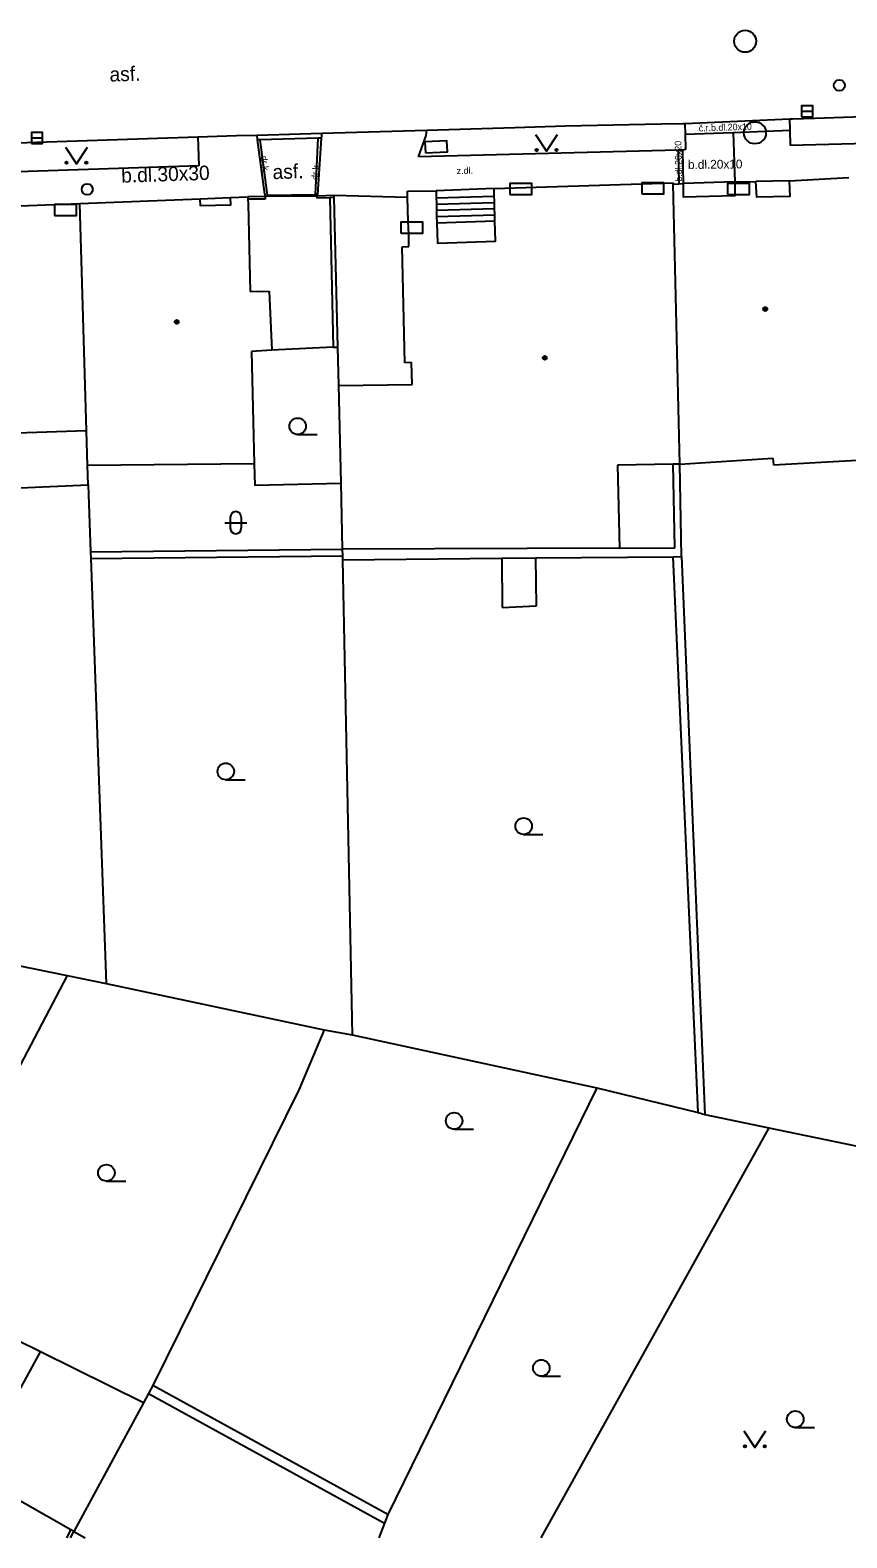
# Model space of a CAD drawing. Extents: x -595546 to -593986, y -1160845 to -1159202.
# Drawn here: x -594974.1 to -594937.1, y -1160843.2 to -1160775 of the extents above; entities that cross this region are included whole.
import ezdxf

# ---------------------------------------------------------------- set-up
doc = ezdxf.new("R2010")
doc.units = 0
for name, color, linetype in [('DOP - kresba z DSPS bez souradnic', 7, 'Continuous'), ('DOP - rozhrani ploch obecne', 7, 'Continuous'), ('Level 24', 7, 'Continuous'), ('Level 27', 7, 'Continuous'), ('Level 28', 7, 'Continuous'), ('Level 36', 7, 'Continuous'), ('Level 39', 7, 'Continuous'), ('TM - budovy zdene_ betonove - NP', 7, 'Continuous'), ('TM - budovy zdene_ betonove - VP', 7, 'Continuous'), ('TM - chodniky - VP', 7, 'Continuous'), ('TM - komunikace - VP', 7, 'Continuous'), ('TM - plot drateny_ kovovy - VP', 7, 'Continuous'), ('TM - podezdivka plotu - VP', 7, 'Continuous'), ('TM - popis povrchu', 7, 'Continuous'), ('TM - rozhrani mezi zpev. plochami mezi sebou - VP', 7, 'Continuous'), ('TM - rozhrani ploch obecne - VP', 7, 'Continuous'), ('TM - schody - VP', 7, 'Continuous'), ('TM - vjezd na pozemek', 7, 'Continuous'), ('TM - vstup do budovy - zdene_ betonove', 7, 'Continuous')]:
    doc.layers.add(name, color=color, linetype=linetype)

msp = doc.modelspace()

# ---------------------------------------------------------------- linework, layer by layer
at = {"layer": 'DOP - kresba z DSPS bez souradnic'}
for points in [[(-594944.87, -1160798.41), (-594944.94, -1160794.62)], [(-594971.35, -1160798.59), (-594959.95, -1160798.46)], [(-594947.38, -1160798.42), (-594944.87, -1160798.41)], [(-594943.81, -1160823.98), (-594944.95, -1160798.81)], [(-594952.71, -1160798.88), (-594951.16, -1160798.86)], [(-594975.24, -1160837.78), (-594973.62, -1160834.82)], [(-594968.73, -1160836.71), (-594958.03, -1160842.58)], [(-594975.4, -1160841.06), (-594972.24, -1160842.87)], [(-594972.24, -1160842.87), (-594972.1, -1160842.95)], [(-594972.1, -1160842.95), (-594971.596, -1160843.241)]]:
    msp.add_lwpolyline(points, dxfattribs=at)
at = {"layer": 'DOP - rozhrani ploch obecne'}
for points in [[(-594971.46, -1160795.55), (-594971.48, -1160794.68)], [(-594944.56, -1160798.8), (-594944.64, -1160794.61)], [(-594979.39, -1160795.9), (-594971.46, -1160795.55)], [(-594971.46, -1160795.55), (-594971.35, -1160798.59)], [(-594971.35, -1160798.59), (-594971.34, -1160798.89)], [(-594971.34, -1160798.89), (-594959.93, -1160798.76)], [(-594959.95, -1160798.46), (-594959.93, -1160798.76)], [(-594959.93, -1160798.76), (-594959.93, -1160798.95)], [(-594951.16, -1160798.86), (-594944.95, -1160798.81)], [(-594944.95, -1160798.81), (-594944.56, -1160798.8)], [(-594944.56, -1160798.8), (-594943.51, -1160824.07)], [(-594971.34, -1160798.89), (-594970.64, -1160818.13)], [(-594959.93, -1160798.95), (-594952.71, -1160798.88)], [(-594959.93, -1160798.95), (-594959.49, -1160820.46)], [(-594952.71, -1160798.88), (-594952.69, -1160801.11)], [(-594951.14, -1160801.03), (-594951.16, -1160798.86)], [(-594952.69, -1160801.11), (-594951.14, -1160801.03)], [(-594978.49, -1160816.54), (-594972.41, -1160817.77)], [(-594972.41, -1160817.77), (-594979.48, -1160831.23)], [(-594972.41, -1160817.77), (-594970.64, -1160818.13)], [(-594970.64, -1160818.13), (-594960.76, -1160820.23)], [(-594960.76, -1160820.23), (-594961.89, -1160822.92), (-594968.53, -1160836.34)], [(-594960.76, -1160820.23), (-594959.49, -1160820.46)], [(-594959.49, -1160820.46), (-594948.41, -1160822.86)], [(-594948.41, -1160822.86), (-594957.88, -1160842.18)], [(-594948.41, -1160822.86), (-594943.81, -1160823.98)], [(-594943.81, -1160823.98), (-594943.51, -1160824.07)], [(-594943.51, -1160824.07), (-594940.6, -1160824.67)], [(-594940.6, -1160824.67), (-594950.935, -1160843.241)], [(-594940.6, -1160824.67), (-594935.43, -1160825.75)], [(-594973.62, -1160834.82), (-594974.72, -1160834.27)], [(-594968.95, -1160837.12), (-594973.62, -1160834.82)], [(-594968.53, -1160836.34), (-594968.73, -1160836.71)], [(-594957.88, -1160842.18), (-594968.53, -1160836.34)], [(-594968.73, -1160836.71), (-594968.95, -1160837.12)], [(-594968.95, -1160837.12), (-594972.1, -1160842.95)], [(-594957.88, -1160842.18), (-594958.03, -1160842.58)], [(-594958.03, -1160842.58), (-594958.284, -1160843.241)]]:
    msp.add_lwpolyline(points, dxfattribs=at)
at = {"layer": 'Level 24'}
for points in [[(-594956.174, -1160780.523), (-594955.175, -1160780.471), (-594955.201, -1160779.972), (-594956.199, -1160780.024)], [(-594952.348, -1160782.399), (-594951.348, -1160782.399), (-594951.348, -1160781.899), (-594952.348, -1160781.899)], [(-594946.367, -1160782.378), (-594945.367, -1160782.378), (-594945.367, -1160781.878), (-594946.367, -1160781.878)], [(-594942.487, -1160782.408), (-594941.487, -1160782.408), (-594941.487, -1160781.908), (-594942.487, -1160781.908)], [(-594972.987, -1160783.358), (-594971.987, -1160783.358), (-594971.987, -1160782.858), (-594972.987, -1160782.858)], [(-594957.288, -1160784.159), (-594956.288, -1160784.159), (-594956.288, -1160783.659), (-594957.288, -1160783.659)]]:
    msp.add_lwpolyline(points, close=True, dxfattribs=at)
at = {"layer": 'Level 27'}
for p, q in [((-594939.12, -1160778.63), (-594938.62, -1160778.63)), ((-594974.03, -1160779.84), (-594973.53, -1160779.84))]:
    msp.add_line(p, q, dxfattribs=at)
for points in [[(-594939.12, -1160778.88), (-594938.62, -1160778.88), (-594938.62, -1160778.38), (-594939.12, -1160778.38)], [(-594974.03, -1160780.09), (-594973.53, -1160780.09), (-594973.53, -1160779.59), (-594974.03, -1160779.59)]]:
    msp.add_lwpolyline(points, close=True, dxfattribs=at)
for centre in [(-594941.68, -1160775.46), (-594941.24, -1160779.61)]:
    msp.add_circle(centre, 0.5, dxfattribs=at)
at = {"layer": 'Level 28'}
for centre in [(-594937.41, -1160777.46), (-594971.5, -1160782.17)]:
    msp.add_circle(centre, 0.25, dxfattribs=at)
at = {"layer": 'Level 36'}
for p, q in [((-594961.96, -1160793.275), (-594961.085, -1160793.275)), ((-594965.266, -1160797.266), (-594964.266, -1160797.266)), ((-594965.016, -1160797.016), (-594965.016, -1160797.516)), ((-594964.516, -1160797.016), (-594964.516, -1160797.516)), ((-594965.22, -1160808.905), (-594964.345, -1160808.905)), ((-594951.72, -1160811.385), (-594950.845, -1160811.385)), ((-594954.87, -1160824.735), (-594953.995, -1160824.735)), ((-594970.63, -1160827.085), (-594969.755, -1160827.085)), ((-594950.92, -1160835.925), (-594950.045, -1160835.925)), ((-594939.41, -1160838.245), (-594938.535, -1160838.245))]:
    msp.add_line(p, q, dxfattribs=at)
for points in [[(-594951.18, -1160779.69), (-594950.68, -1160780.44), (-594950.18, -1160779.69)], [(-594972.49, -1160780.26), (-594971.99, -1160781.01), (-594971.49, -1160780.26)], [(-594941.74, -1160838.4), (-594941.24, -1160839.15), (-594940.74, -1160838.4)]]:
    msp.add_lwpolyline(points, dxfattribs=at)
for centre, radius in [((-594951.13, -1160780.39), 0.05), ((-594950.231, -1160780.39), 0.05), ((-594972.44, -1160780.96), 0.05), ((-594971.541, -1160780.96), 0.05), ((-594961.96, -1160792.9), 0.375), ((-594965.22, -1160808.53), 0.375), ((-594951.72, -1160811.01), 0.375), ((-594954.87, -1160824.36), 0.375), ((-594970.63, -1160826.71), 0.375), ((-594950.92, -1160835.55), 0.375), ((-594939.41, -1160837.87), 0.375), ((-594941.69, -1160839.1), 0.05), ((-594940.791, -1160839.1), 0.05)]:
    msp.add_circle(centre, radius, dxfattribs=at)
for centre, start, end in [((-594964.766, -1160797.016), 0, 180), ((-594964.766, -1160797.516), 180, 0)]:
    msp.add_arc(centre, 0.25, start, end, dxfattribs=at)
at = {"layer": 'Level 39'}
for centre, radius in [((-594940.77, -1160787.59), 0.09), ((-594940.77, -1160787.59), 0.0398), ((-594967.44, -1160788.17), 0.09), ((-594967.44, -1160788.17), 0.0398), ((-594950.76, -1160789.8), 0.09), ((-594950.76, -1160789.8), 0.0398)]:
    msp.add_circle(centre, radius, dxfattribs=at)
at = {"layer": 'TM - budovy zdene_ betonove - NP'}
for points in [[(-594955.69, -1160782.24), (-594955.67, -1160783.12), (-594955.67, -1160783.4), (-594955.66, -1160783.68), (-594955.63, -1160784.6), (-594953, -1160784.52), (-594953.03, -1160783.6), (-594953.03, -1160783.32), (-594953.04, -1160783.03), (-594953.06, -1160782.13)], [(-594942.15, -1160781.83), (-594942.15, -1160782.46), (-594944.47, -1160782.52), (-594944.48, -1160781.91)], [(-594939.69, -1160781.78), (-594939.66, -1160782.5), (-594941.15, -1160782.53), (-594941.19, -1160781.82)], [(-594965.02, -1160782.54), (-594965.01, -1160782.88), (-594966.37, -1160782.92), (-594966.38, -1160782.6)]]:
    msp.add_lwpolyline(points, dxfattribs=at)
at = {"layer": 'TM - budovy zdene_ betonove - VP'}
for points in [[(-594939.69, -1160781.78), (-594936.98, -1160781.63)], [(-594956.99, -1160782.25), (-594955.69, -1160782.24)], [(-594956.98, -1160782.54), (-594956.99, -1160782.25)], [(-594953.06, -1160782.13), (-594944.94, -1160781.88)], [(-594944.94, -1160781.88), (-594944.94, -1160781.93)], [(-594944.94, -1160781.93), (-594944.68, -1160781.92)], [(-594944.64, -1160794.61), (-594944.94, -1160781.93)], [(-594944.68, -1160781.92), (-594944.48, -1160781.91)], [(-594942.15, -1160781.83), (-594941.19, -1160781.82)], [(-594979.78, -1160783.11), (-594977.28, -1160783.021), (-594971.84, -1160782.81)], [(-594971.84, -1160782.81), (-594966.38, -1160782.6)], [(-594971.54, -1160793.11), (-594971.84, -1160782.81)], [(-594966.38, -1160782.6), (-594965.02, -1160782.54)], [(-594965.02, -1160782.54), (-594964.22, -1160782.51)], [(-594964.22, -1160782.51), (-594964.22, -1160782.62)], [(-594964.22, -1160782.62), (-594964.21, -1160782.82)], [(-594964.21, -1160782.82), (-594964.11, -1160786.8)], [(-594956.92, -1160784.76), (-594956.93, -1160784.21), (-594956.95, -1160783.61), (-594956.98, -1160782.54)], [(-594957.22, -1160784.77), (-594956.92, -1160784.76)], [(-594957.1, -1160790.02), (-594957.22, -1160784.77)], [(-594964.11, -1160786.8), (-594963.25, -1160786.78)], [(-594963.25, -1160786.78), (-594963.13, -1160789.46)], [(-594963.13, -1160789.46), (-594964.05, -1160789.51)], [(-594964.05, -1160789.51), (-594963.93, -1160794.6)], [(-594956.8, -1160790.01), (-594957.1, -1160790.02)], [(-594956.77, -1160791.01), (-594956.8, -1160790.01)], [(-594960.11, -1160791.05), (-594956.77, -1160791.01)], [(-594960.11, -1160791.05), (-594960.01, -1160795.48)], [(-594971.54, -1160793.11), (-594977.86, -1160793.32)], [(-594971.48, -1160794.68), (-594971.54, -1160793.11)], [(-594963.93, -1160794.6), (-594971.48, -1160794.68)], [(-594944.94, -1160794.62), (-594947.47, -1160794.66)], [(-594947.47, -1160794.66), (-594947.38, -1160798.42)], [(-594944.64, -1160794.61), (-594944.94, -1160794.62)], [(-594944.64, -1160794.61), (-594940.43, -1160794.34)], [(-594940.43, -1160794.34), (-594940.4, -1160794.64)], [(-594940.4, -1160794.64), (-594936.6, -1160794.43)], [(-594960.01, -1160795.48), (-594959.95, -1160798.46)], [(-594947.38, -1160798.42), (-594959.95, -1160798.46)]]:
    msp.add_lwpolyline(points, dxfattribs=at)
at = {"layer": 'TM - chodniky - VP'}
for points in [[(-594939.64, -1160779.49), (-594939.65, -1160778.98)], [(-594956.49, -1160780.69), (-594956.14, -1160779.73)], [(-594956.14, -1160779.73), (-594956.11, -1160779.49)], [(-594944.41, -1160779.18), (-594944.4, -1160779.67)], [(-594944.4, -1160779.67), (-594944.39, -1160780.37)], [(-594939.62, -1160780.19), (-594939.64, -1160779.49)], [(-594966.49, -1160779.79), (-594966.44, -1160781.11)], [(-594944.71, -1160780.4), (-594956.49, -1160780.69)], [(-594944.51, -1160780.4), (-594944.71, -1160780.4)], [(-594944.39, -1160780.37), (-594944.51, -1160780.4)], [(-594926.94, -1160779.85), (-594939.62, -1160780.19)], [(-594966.44, -1160781.11), (-594980.11, -1160781.56)]]:
    msp.add_lwpolyline(points, dxfattribs=at)
at = {"layer": 'TM - komunikace - VP'}
for points in [[(-594944.41, -1160779.18), (-594939.65, -1160778.98)], [(-594939.65, -1160778.98), (-594939.53, -1160778.98)], [(-594939.53, -1160778.98), (-594938.52, -1160778.95)], [(-594938.52, -1160778.95), (-594936.79, -1160778.89), (-594928.05, -1160778.6)], [(-594966.49, -1160779.79), (-594964.73, -1160779.73)], [(-594964.73, -1160779.73), (-594963.79, -1160779.71)], [(-594963.79, -1160779.71), (-594960.87, -1160779.63)], [(-594960.87, -1160779.63), (-594956.11, -1160779.49)], [(-594956.11, -1160779.49), (-594952.12, -1160779.37), (-594949.82, -1160779.3)], [(-594949.82, -1160779.3), (-594945.48, -1160779.2)], [(-594945.48, -1160779.2), (-594944.5, -1160779.18)], [(-594944.5, -1160779.18), (-594944.41, -1160779.18)], [(-594979.27, -1160780.21), (-594966.49, -1160779.79)]]:
    msp.add_lwpolyline(points, dxfattribs=at)
at = {"layer": 'TM - plot drateny_ kovovy - VP'}
for points in [[(-594963.43, -1160782.61), (-594964.22, -1160782.62)], [(-594960.51, -1160782.55), (-594961.1, -1160782.57)], [(-594960.32, -1160782.54), (-594960.51, -1160782.55)], [(-594960.51, -1160782.55), (-594960.35, -1160789.32)], [(-594960.35, -1160789.32), (-594960.15, -1160789.31)], [(-594972.24, -1160842.87), (-594972.442, -1160843.241)]]:
    msp.add_lwpolyline(points, dxfattribs=at)
at = {"layer": 'TM - podezdivka plotu - VP'}
for points in [[(-594960.32, -1160782.45), (-594961.05, -1160782.48)], [(-594960.32, -1160782.45), (-594960.32, -1160782.54)], [(-594963.44, -1160782.49), (-594964.22, -1160782.51)], [(-594963.44, -1160782.49), (-594963.43, -1160782.61)], [(-594961.1, -1160782.48), (-594961.1, -1160782.57)], [(-594961.05, -1160782.48), (-594961.1, -1160782.48)], [(-594960.32, -1160782.54), (-594960.15, -1160789.31)], [(-594960.15, -1160789.31), (-594960.11, -1160791.05)], [(-594972.257, -1160843.241), (-594972.1, -1160842.95)]]:
    msp.add_lwpolyline(points, dxfattribs=at)
at = {"layer": 'TM - rozhrani mezi zpev. plochami mezi sebou - VP'}
for points in [[(-594963.78, -1160779.92), (-594963.79, -1160779.71)], [(-594960.87, -1160779.63), (-594960.9, -1160779.85)], [(-594944.4, -1160779.67), (-594942.22, -1160779.6)], [(-594942.22, -1160779.6), (-594939.64, -1160779.49)], [(-594942.22, -1160779.6), (-594942.15, -1160781.83)], [(-594963.45, -1160782.39), (-594963.78, -1160779.92)], [(-594963.67, -1160779.92), (-594963.78, -1160779.92)], [(-594961.03, -1160779.85), (-594963.67, -1160779.92)], [(-594963.67, -1160779.92), (-594963.34, -1160782.43)], [(-594961.16, -1160782.4), (-594961.03, -1160779.85)], [(-594960.9, -1160779.85), (-594961.06, -1160782.41)], [(-594960.9, -1160779.85), (-594961.03, -1160779.85)], [(-594944.71, -1160780.4), (-594944.68, -1160781.92)], [(-594944.48, -1160781.91), (-594944.51, -1160780.4)], [(-594963.45, -1160782.39), (-594963.44, -1160782.49)], [(-594963.34, -1160782.43), (-594961.16, -1160782.4)], [(-594961.06, -1160782.41), (-594961.16, -1160782.4)], [(-594961.06, -1160782.41), (-594961.05, -1160782.48)]]:
    msp.add_lwpolyline(points, dxfattribs=at)
at = {"layer": 'TM - rozhrani ploch obecne - VP'}
for points in [[(-594960.35, -1160789.32), (-594963.13, -1160789.46)], [(-594963.93, -1160794.6), (-594963.91, -1160795.57), (-594960.01, -1160795.48)]]:
    msp.add_lwpolyline(points, dxfattribs=at)
at = {"layer": 'TM - schody - VP'}
for points in [[(-594955.68, -1160782.56), (-594953.05, -1160782.48)], [(-594955.68, -1160782.84), (-594953.05, -1160782.76)], [(-594955.67, -1160783.12), (-594953.04, -1160783.03)], [(-594955.67, -1160783.4), (-594953.03, -1160783.32)], [(-594955.66, -1160783.68), (-594953.03, -1160783.6)]]:
    msp.add_lwpolyline(points, dxfattribs=at)
at = {"layer": 'TM - vjezd na pozemek'}
for points in [[(-594956.98, -1160782.54), (-594960.32, -1160782.45)], [(-594961.1, -1160782.48), (-594963.44, -1160782.49)]]:
    msp.add_lwpolyline(points, dxfattribs=at)
at = {"layer": 'TM - vstup do budovy - zdene_ betonove'}
for points in [[(-594953.06, -1160782.13), (-594955.69, -1160782.24)], [(-594942.15, -1160781.83), (-594944.48, -1160781.91)], [(-594939.69, -1160781.78), (-594941.19, -1160781.82)]]:
    msp.add_lwpolyline(points, dxfattribs=at)

# ---------------------------------------------------------------- texts
at = {"layer": 'TM - popis povrchu'}
for s, height, rotation, p in [('asf.', 0.65, 1.83171, (-594970.48, -1160777.29)), ('č.r.b.dl.20x10', 0.3, 1.90784, (-594943.78, -1160779.55)), ('b.dl.20x20', 0.3, 91, (-594944.54, -1160781.82)), ('b.dl.30x30', 0.65, 1.88854, (-594969.95, -1160781.87)), ('dr.k.', 0.3, 277, (-594963.64, -1160780.67)), ('asf.', 0.65, 1.88854, (-594963.09, -1160781.71)), ('dr.k.', 0.3, 87, (-594961.03, -1160781.75)), ('b.dl.20x10', 0.4, 0.69789, (-594944.27, -1160781.25)), ('z.dl.', 0.3, 1.72448, (-594954.75, -1160781.48))]:
    msp.add_text(s, height=height, rotation=rotation, dxfattribs=at).set_placement(p)

doc.saveas('drawing.dxf')
